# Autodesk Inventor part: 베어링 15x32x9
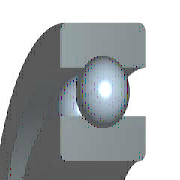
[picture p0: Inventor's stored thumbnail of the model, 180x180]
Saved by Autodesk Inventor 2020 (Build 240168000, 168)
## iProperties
Created: 2012-02
Part Number: 베어링 15x32x9
Material: 강철, 연강
Description: 깊은 그루브 볼 베어링
Document SubType Name: Modeling
Standard: KS B 2023
Designer: mduedu
Standards Organization: KS
Language: ko-KR
Size Designation: 6002 - 15 x 32 x 9
Categories: <MemberInstance><Categories><Category DisplayName="샤프트 부품" InternalName="7f7aeb1f-a693-4053-b835-cee3144e0d98" Mnemonic="SHFT"><Category DisplayName="베어링" Inter
Density: 1 g/cm^3
Appearance: 노란색
IsCustomPart: 0
Author: mduedu
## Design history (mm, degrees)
sketch "스케치" dims "d0" = 4.42 (= -0.26 x WD + 0.26 x BD)
  geometry: L1 (2.29, 11.75)-(6.71, 11.75); L2 (4.5, 11.75)-(4.5, 9.54); L3 (4.5, 11.75)-(4.5, 13.96); L4 (2.858, 10.271)-(0, 10.271); L5 (0, 7.5)-(9, 7.5); L6 (2.858, 13.229)-(0, 13.229); L7 (0, 16)-(9, 16); L8 (9, 7.5)-(9, 10.271); L9 (6.142, 10.271)-(9, 10.271); L10 (6.142, 13.229)-(9, 13.229); L11 (9, 16)-(9, 13.229); L12 (-1.4, 0)-(8.4, 0) reference; L13 (0, -0.3)-(0, 5.3) reference
  constraints: 22 end point, 4 point on line, 2 collinear, 2 perpendicular, 2 symmetric about line, 1 midpoint, 1 parallel, 14 other
  dimensions: "d9" = 15 diameter of L5 L12 (= WD); "d11" = 32 diameter of L7 L12 (= BD); "d12" = 9 distance between parallel lines of L8 L13 (= KB); "d13" = 20.542 diameter of L9 L12 (= 0.326 x BD + 0.674 x WD)
revolve "본체" stored, may be unused: angle "d6" = 90 deg
revolve "볼" stored, may be unused: angle "d7" = 90 deg
pattern_circular "IDS_ARRAYBALL[SIMPL:T]" dims angle "d3" = 360 deg
body "Solid1"
fillet "모깎기1" dims "d1" = 0.3 (= KRS)
other parameters: "WD" = 15 [user parameter; used in 5 equation terms], "BD" = 32 [user parameter; used in 5 equation terms], "KB" = 9 [user parameter; used in 1 equation term], "KRS" = 0.3 [user parameter; used in 1 equation term], "d4" = 0, "d5" = 0, "d8" = 0, "d14" = 0, "d15" = 0, "BBA" = 0 [user parameter], "BC0" = 2850000 [user parameter], "BC" = 5590000 [user parameter], "BR" = 16 (= 0.5 x BD) [user parameter], "WR" = 7.5 (= 0.5 x WD) [user parameter]
